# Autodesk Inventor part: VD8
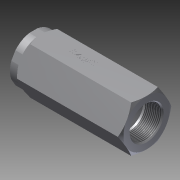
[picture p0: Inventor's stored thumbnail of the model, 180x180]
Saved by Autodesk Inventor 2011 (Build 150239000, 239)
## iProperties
Created: 2012-01
Part Number: VD8
Document SubType Name: Modeling
Designer: khramov
Density: 1 g/cm^3
Author: khramov
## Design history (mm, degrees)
derived "VD8_W1_30.ipt"
feature "Твердое тело1::VD8_W1_30.ipt" dims "d0" = 10
tag "Элемент создания маркировки1"
node "Твердое тело1"
